(* Logix 5000 project; controller Terminal_ENet_Integer vendor 1 type 14 code 51 rev 16.3; software revision 16.03 *)

TASK MainTask (continuous, watchdog 500 ms) : MainProgram

MODULES
   Local : vendor 1 type 14 code 51 (ICP 0, rev 16.3)
      ENet_Interface : vendor 1 type 12 code 20 (ICP 1, Ethernet 192.168.0.30, rev 2.7)
         Terminal : ETHERNET-MODULE (Ethernet 192.168.0.33, rev 1.1, Output RPI 10 ms)
              Terminal:I.DATA[0]   // Weight Data
              Terminal:I.DATA[2]   // Slot 2 Weight Data
              Terminal:I.DATA[4]   // Slot 3 Weight Data
              Terminal:I.DATA[6]   // Slot 4 Weight Data
              Terminal:I.DATA[1].15   // Data OK
              Terminal:I.DATA[3].15   // Data OK
              Terminal:I.DATA[5].15   // Data OK
              Terminal:I.DATA[7].15   // Data OK
              Terminal:I.DATA[1]   // Scale Status
              Terminal:I.DATA[3]   // Slot 2 Scale Status
              Terminal:I.DATA[5]   // Slot 3 Scale Status
              Terminal:I.DATA[7]   // Slot 4 Scale Status
              Terminal:O.DATA[0]   // Tare/Target Value
              Terminal:O.DATA[2]   // Slot 2 Tare/Target Value
              Terminal:O.DATA[4]   // Slot 3 Tare/Target Value
              Terminal:O.DATA[6]   // Slot 4 Tare/Target Value
              Terminal:O.DATA[1]   // Scale Commands
              Terminal:O.DATA[3]   // Slot 2 Scale Commands
              Terminal:O.DATA[5]   // Slot 3 Scale Commands
              Terminal:O.DATA[7]   // Slot 4 Scale Commands
END_MODULES

ADD_ON_INSTRUCTION IND131_331_IntDiv_Input_Data   (* revision 1.0 *)
// Integer/Divisions input data parsing
// Help:
// Slot_Input_1st_INT is data type INT; must point to the first Integer of the input message
// Slot_Input_2nd_INT is data type INT; must point to the second Integer of the input message.
// Increment_Size is data type REAL; must match scale calibration increment size; default is one (1).
// Use_Divisions is a data Type BOOL set to ON (1) if Divisions Data Type is used; default is Integer Data Type.
VAR_IN_OUT
   Input_1st_INT : INT; {required}   // 1st Word of Input Data
        [0]   // Weight input data
        [1]   // Status Input Data
   Input_2nd_INT : INT; {required}   // 2nd Word of Input Data
END_VAR
VAR_INPUT
   Increment_Size : REAL; {visible}   // Scale Calibration Increment Size
   Use_Divisions : BOOL; {visible}   // Perform Divisions convertion
END_VAR
VAR_OUTPUT
   Weight : REAL;   // Weight Data in a Real
   Feed_Under : BOOL;   // Target Feed bit or Over/Under logic OK bit
   FastFeed_OK : BOOL;   // Target Fast Feed bit or Over/Under logic OK bit
   TolOK_Over : BOOL;   // Target Tolerance OK bit or Over/Under Logic Over bit
   Compar_3 : BOOL;   // Comparator 3 Status bit
   Compar_2 : BOOL;   // Comparator 2 Status bit
   Compar_1 : BOOL;   // Comparator 1 Status bit
   Discrete_In_1 : BOOL;   // Input 1 (0.0.1) status bit
   Discrete_In_2 : BOOL;   // Input 2 (0.0.2) status bit
   Motion : BOOL;   // Motion Status bit
   Net_Mode : BOOL;   // Net Mode Status bit
   UpDate_InProcess : BOOL;   // Update in Process bit
   Data_OK : BOOL;   // Data OK bit
END_VAR
VAR
   Inc_Mulitiplier : REAL;
   Inc_Divider : REAL;
END_VAR

ROUTINE Logic   (* ladder *)
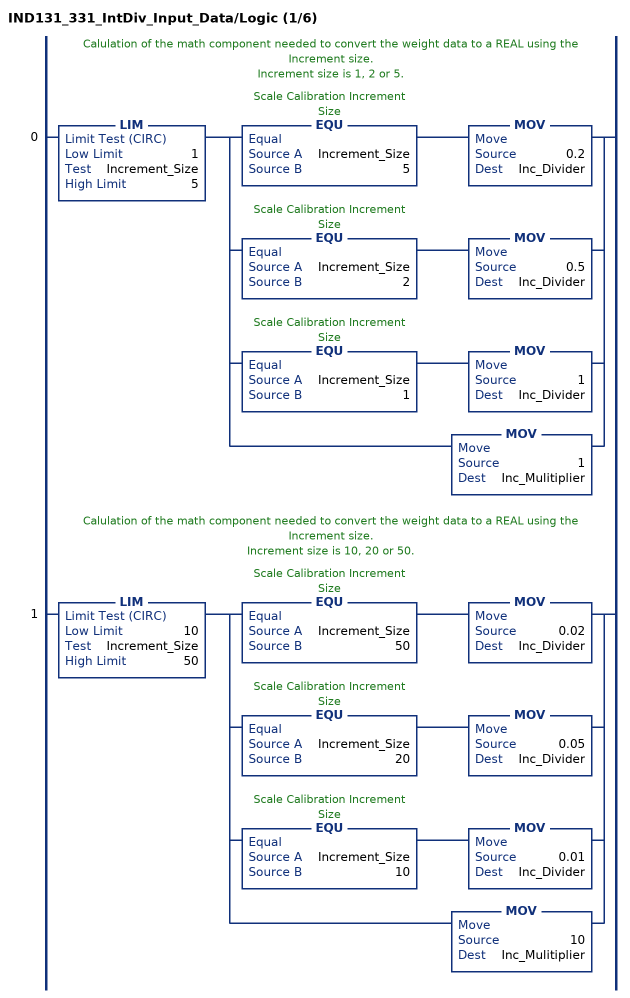
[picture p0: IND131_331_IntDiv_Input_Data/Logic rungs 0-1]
   // Calulation of the math component needed to convert the weight data to a REAL using the Increment size.
   // Increment size is 1, 2 or 5.
   0: LIM(1,Increment_Size,5)[EQU(Increment_Size,5) MOV(0.2,Inc_Divider) ,EQU(Increment_Size,2) MOV(0.5,Inc_Divider) ,EQU(Increment_Size,1) MOV(1,Inc_Divider) ,MOV(1,Inc_Mulitiplier) ];
   // Calulation of the math component needed to convert the weight data to a REAL using the Increment size.
   // Increment size is 10, 20 or 50.
   1: LIM(10,Increment_Size,50)[EQU(Increment_Size,50) MOV(0.02,Inc_Divider) ,EQU(Increment_Size,20) MOV(0.05,Inc_Divider) ,EQU(Increment_Size,10) MOV(0.01,Inc_Divider) ,MOV(10,Inc_Mulitiplier) ];
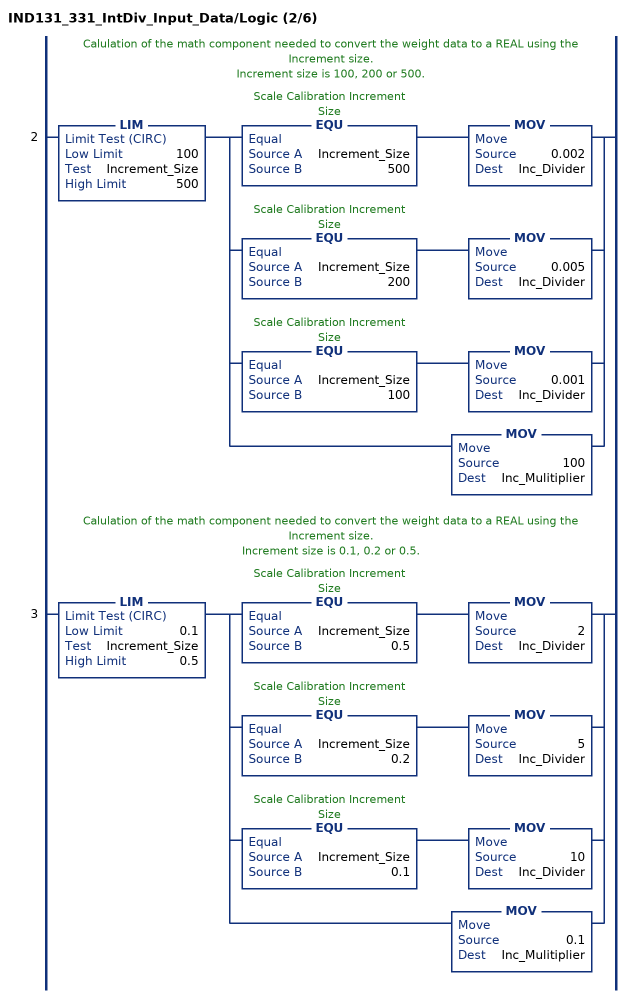
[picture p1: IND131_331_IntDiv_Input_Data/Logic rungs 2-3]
   // Calulation of the math component needed to convert the weight data to a REAL using the Increment size.
   // Increment size is 100, 200 or 500.
   2: LIM(100,Increment_Size,500)[EQU(Increment_Size,500) MOV(0.002,Inc_Divider) ,EQU(Increment_Size,200) MOV(0.005,Inc_Divider) ,EQU(Increment_Size,100) MOV(0.001,Inc_Divider) ,MOV(100,Inc_Mulitiplier) ];
   // Calulation of the math component needed to convert the weight data to a REAL using the Increment size.
   // Increment size is 0.1, 0.2 or 0.5.
   3: LIM(0.1,Increment_Size,0.5)[EQU(Increment_Size,0.5) MOV(2,Inc_Divider) ,EQU(Increment_Size,0.2) MOV(5,Inc_Divider) ,EQU(Increment_Size,0.1) MOV(10,Inc_Divider) ,MOV(0.1,Inc_Mulitiplier) ];
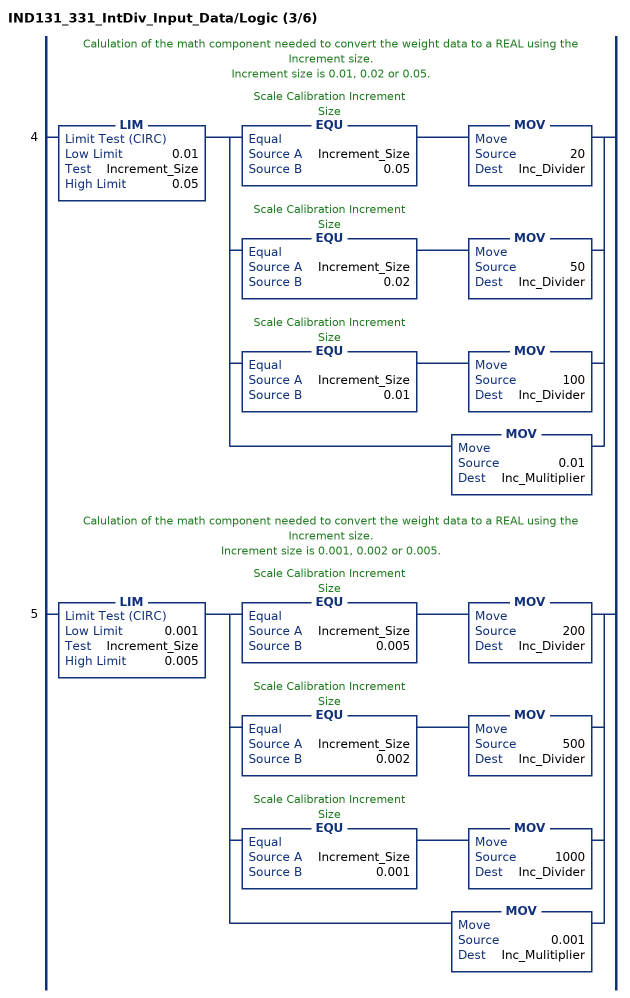
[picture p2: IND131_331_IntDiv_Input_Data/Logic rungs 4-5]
   // Calulation of the math component needed to convert the weight data to a REAL using the Increment size.
   // Increment size is 0.01, 0.02 or 0.05.
   4: LIM(0.01,Increment_Size,0.05)[EQU(Increment_Size,0.05) MOV(20,Inc_Divider) ,EQU(Increment_Size,0.02) MOV(50,Inc_Divider) ,EQU(Increment_Size,0.01) MOV(100,Inc_Divider) ,MOV(0.01,Inc_Mulitiplier) ];
   // Calulation of the math component needed to convert the weight data to a REAL using the Increment size.
   // Increment size is 0.001, 0.002 or 0.005.
   5: LIM(0.001,Increment_Size,0.005)[EQU(Increment_Size,0.005) MOV(200,Inc_Divider) ,EQU(Increment_Size,0.002) MOV(500,Inc_Divider) ,EQU(Increment_Size,0.001) MOV(1000,Inc_Divider) ,MOV(0.001,Inc_Mulitiplier) ];
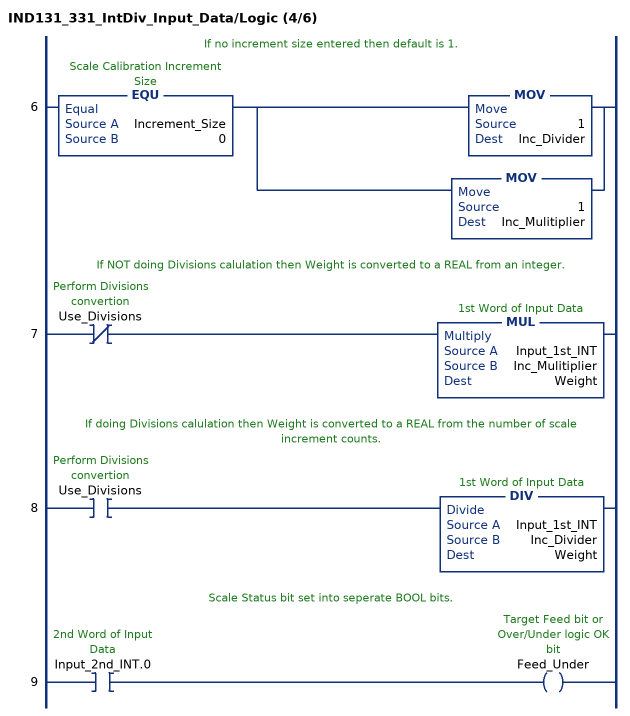
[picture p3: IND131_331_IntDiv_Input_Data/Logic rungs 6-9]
   // If no increment size entered then default is 1.
   6: EQU(Increment_Size,0)[MOV(1,Inc_Divider) ,MOV(1,Inc_Mulitiplier) ];
   // If NOT doing Divisions calulation then Weight is converted to a REAL from an integer.
   7: XIO(Use_Divisions)MUL(Input_1st_INT,Inc_Mulitiplier,Weight);
   // If doing Divisions calulation then Weight is converted to a REAL from the number of scale increment counts.
   8: XIC(Use_Divisions)DIV(Input_1st_INT,Inc_Divider,Weight);
   // Scale Status bit set into seperate BOOL bits.
   9: XIC(Input_2nd_INT.0)OTE(Feed_Under);
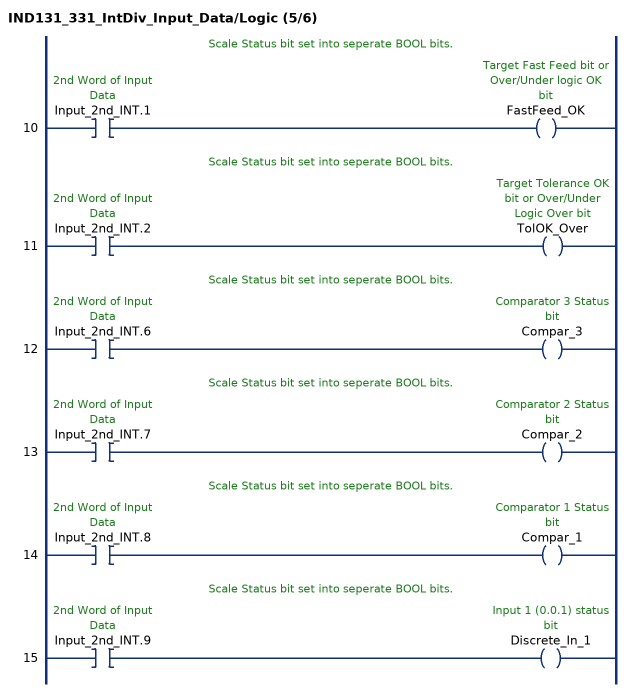
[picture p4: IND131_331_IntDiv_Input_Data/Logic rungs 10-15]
   // Scale Status bit set into seperate BOOL bits.
   10: XIC(Input_2nd_INT.1)OTE(FastFeed_OK);
   // Scale Status bit set into seperate BOOL bits.
   11: XIC(Input_2nd_INT.2)OTE(TolOK_Over);
   // Scale Status bit set into seperate BOOL bits.
   12: XIC(Input_2nd_INT.6)OTE(Compar_3);
   // Scale Status bit set into seperate BOOL bits.
   13: XIC(Input_2nd_INT.7)OTE(Compar_2);
   // Scale Status bit set into seperate BOOL bits.
   14: XIC(Input_2nd_INT.8)OTE(Compar_1);
   // Scale Status bit set into seperate BOOL bits.
   15: XIC(Input_2nd_INT.9)OTE(Discrete_In_1);
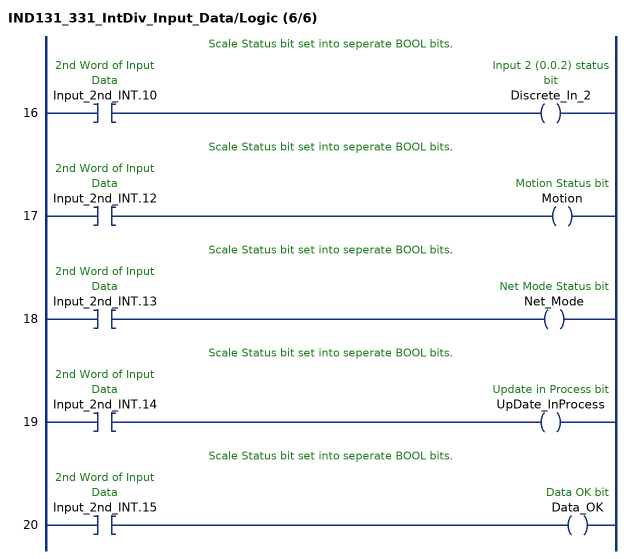
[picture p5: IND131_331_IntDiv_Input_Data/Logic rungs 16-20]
   // Scale Status bit set into seperate BOOL bits.
   16: XIC(Input_2nd_INT.10)OTE(Discrete_In_2);
   // Scale Status bit set into seperate BOOL bits.
   17: XIC(Input_2nd_INT.12)OTE(Motion);
   // Scale Status bit set into seperate BOOL bits.
   18: XIC(Input_2nd_INT.13)OTE(Net_Mode);
   // Scale Status bit set into seperate BOOL bits.
   19: XIC(Input_2nd_INT.14)OTE(UpDate_InProcess);
   // Scale Status bit set into seperate BOOL bits.
   20: XIC(Input_2nd_INT.15)OTE(Data_OK);
END_ROUTINE
END_ADD_ON_INSTRUCTION

VAR_GLOBAL   (* controller tags *)
   Scale1 : IND131_331_IntDiv_Input_Data;
END_VAR

PROGRAM MainProgram   (* main routine MainRoutine *)

ROUTINE MainRoutine   (* ladder *)
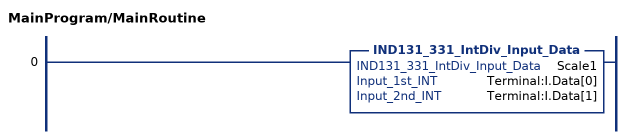
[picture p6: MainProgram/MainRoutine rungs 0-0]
   0: IND131_331_IntDiv_Input_Data(Scale1,Terminal:I.Data[0],Terminal:I.Data[1]);
END_ROUTINE
END_PROGRAM
